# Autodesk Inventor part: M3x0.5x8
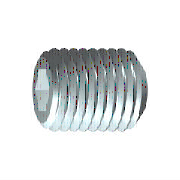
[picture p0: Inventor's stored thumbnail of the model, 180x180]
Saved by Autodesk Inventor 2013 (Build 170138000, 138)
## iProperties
IsCustomPart: 1
Company: 한국ATC센터
Created: 2009-02
Part Number: M3x0.5x8
Material: 강, 연강
Description: 6각 소켓 머리 없는 멈춤 나사
Document SubType Name: Modeling
Standard: KS B 1028
Designer: KYOUNG IL JANG
Standards Organization: KS
Language: ko-KR
Size Designation: 납작점M3x6
Categories: <MemberInstance><Categories><Category DisplayName="조임쇠" InternalName="e4da775c-781d-43d5-af7c-5136215cf5a6" Mnemonic="FSTN"><Category DisplayName="볼트" InternalN
Density: 7.86 g/cm^3
Mass: 0.293227 g
Surface Area: 0.779766 cm^2
Volume: 0.0373062 cm^3
Vendor: CBT Solutions
Author: KYOUNG IL JANG
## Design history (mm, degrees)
sketch "스케치1"
  geometry: L1 (0, 0)-(3.5, 0); L2 (6, 0.866)-(6, 1.5); L3 (6, 1.5)-(0, 1.5); L4 (6, 0.866)-(4, 0.866); L5 (4, 0.866)-(3.5, 0); L6 (0, -0.3)-(0, 1.8) reference; L7 (0, 1.5)-(0, 0)
  constraints: 13 end point, 3 parallel, 1 collinear, 1 perpendicular, 1 point on line
  dimensions: "d0" = 2 distance of L2.start L4.end (= INTI); "d1" = 60 deg angle of L5 L1; "d2" = 3 diameter of L3 L1 (= NND); "d3" = 1.73205 diameter of L4 L1 (= 1.1547 x SW); "d5" = 6 distance from line of L2 L3.end (= NLG)
revolve "본체" sketch "스케치1" stored, may be unused: angle "d6" = 90 deg
sketch "스케치2"
  geometry: L1 (-0.433, 0.75)-(0.433, 0.75); L2 (0.433, 0.75)-(0.866, 0); L3 (0.866, 0)-(0.433, -0.75); L4 (0.433, -0.75)-(-0.433, -0.75); L5 (-0.433, -0.75)-(-0.866, 0); L6 (-0.866, 0)-(-0.433, 0.75); A1 r 0.866 centre (0, 0) between (-0.433, 0.75) and (0.433, 0.75) reference; 2 further points
  constraints: 12 end point, 2 point on circle, 1 coincident, 1 horizontal, 11 other
extrude "슬롯" join sketch "스케치2" taper "d9" = 0 deg; stored distance "d21" = 10
workaxis "Work Axis1"
workplane "Work Plane1"
body "Solid1"
chamfer "모따기1" distance "d7" = 0.30673 (= -0.5 x GD1 + 0.5 x NND); stored, may be unused: angle "d8" = 45 deg (= FAWI), second distance "d29" = 0.30673 (= -0.5 x GD1 + 0.5 x NND)
feature "스레드" dims "d11" = 6 (= NLG), "d12" = 0
chamfer "모따기2" distance "d13" = 0.30673 (= -0.5 x GD1 + 0.5 x NND); stored, may be unused: angle "d14" = 45 deg (= FAWI), second distance "d30" = 0.30673 (= -0.5 x GD1 + 0.5 x NND)
other parameters: "NND" = 3 [user parameter; used in 5 equation terms], "NLG" = 6 [user parameter; used in 2 equation terms], "INTI" = 2 [user parameter; used in 1 equation term], "FAWI" = 45 deg [user parameter; used in 2 equation terms], "SW" = 1.5 [user parameter; used in 2 equation terms], "GD1" = 2.38655 (= THREADDIA - 1.2269 x PTC) [user parameter; used in 4 equation terms], "d4" = 0, "FAWI1" = 45 deg [user parameter], "d15" = 0, "d31" = 0, "GUL" = 0.30673 (= 0.61345 x PTC) [user parameter], "SPD" = 2 [user parameter], "TOA" = 30 deg [user parameter], "THREADDIA" = 3 [user parameter; used in 1 equation term], "PTC" = 0.5 [user parameter; used in 4 equation terms], "GAL" = 0.30673 (= 0.61345 x PTC) [user parameter], "E0" = 1.7325 (= 1.155 x SW) [user parameter]
